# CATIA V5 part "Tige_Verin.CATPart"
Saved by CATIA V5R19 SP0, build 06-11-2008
Part number: Tige_Verin
Bounding box of the stored display mesh (mm): x -3 to 221.32, y -15 to 15, z -17.5 to 17.5
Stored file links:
  G:\EU_thinkMotion\CFAO_2010\MMS_groupe1\MMS_groupe1\OK\vduret\vduret\CATIA\Tige_Verin.CATPart
  G:\EU_thinkMotion\CFAO_2010\MMS_groupe1\MMS_groupe1\OK\vduret\vduret\CATIA\Corps_Verin.CATPart
  G:\EU_thinkMotion\CFAO_2010\MMS_groupe1\MMS_groupe1\OK\vduret\vduret\CATIA\Profile_bati.CATPart
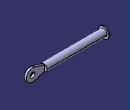
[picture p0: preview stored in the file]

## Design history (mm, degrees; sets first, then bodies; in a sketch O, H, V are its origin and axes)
Parameters
  Longueur_tige_verin = 170 mm
External parameters (linked from other documents)
  External.Diam_tige_verin = 20 mm
  External.Longueur_corps_verin = 150 mm
  External.Diam_corps_verin = 35 mm
  External.Diam_piston_verin = 30 mm
  External.Largeur_bati = 500 mm
Body1 (main body)
  Sketch1 on yz-plane, origin (0, 0, 0), H (0, 1, 0), V (0, 0, 1)
    circle A1 centre (0, 0) radius 10
    radius A1 = 10 {= External.Diam_tige_verin /2}
  Pad1: profile Sketch1, direction (1, 0, 0), length 170 {= Longueur_tige_verin}
  Sketch2 on zx-plane, origin (0, 0, 0), H (-1, 0, 0), V (0, 0, 1)
    arc A1 centre (-204, 0) radius 17.5 from (-198.934, 16.7507) to (-198.934, -16.7507) ccw
    point P1 (-204, 0)
    reference projected line E1 (-170, -10) -> (-170, 10) from edge [face of Pad1 from Sketch1.A1 | end face of Pad1]
    line L1 (-170, 8) -> (-198.934, 16.7507)
    point P2 (-170, 8)
    line L2 (-170, -8) -> (-198.934, -16.7507)
    point P3 (-170, -8)
    reference projected line E2 (-170, -10) -> (-170, 10) from edge [face of Pad1 from Sketch1.A1 | end face of Pad1]
    reference projected line E3 (-170, -10) -> (-170, 10) from edge [face of Pad1 from Sketch1.A1 | end face of Pad1]
    line L3 (-170, 8) -> (-170, -8)
    circle A2 centre (-204, 0) radius 7
    radius A1 = 17.5 {= External.Diam_corps_verin /2}
    distance P1 E1 = 34
    distance P2 H = 8 {= External.Diam_tige_verin /2-2mm}
    distance P3 H = 8 {= External.Diam_tige_verin /2-2mm}
    radius A2 = 7
    coincidence: E2 P2, E3 P3, P1 H
    tangency: L1 A1, L2 A1
    vertical: L3 V
  Pad2: profile Sketch2, direction (0, 1, 0), length 3, mirrored extent
  Sketch3 on start face of Pad1, origin (0, 0, 0), H (0, -1, 0), V (0, 0, 1)
    circle A1 centre (0, 0) radius 15
    radius A1 = 15 {= External.Diam_piston_verin /2}
  Pad3: profile Sketch3, direction (-1, 0, 0), length 3
  Point1: type Center, Curve edge [end face of Pad2 | face of Pad2 from Sketch2.A2]
Relations
  Pad1.FirstLimit.Length = Longueur_tige_verin `Paramètres externes\Largeur_bati` -320mm (deactivated)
